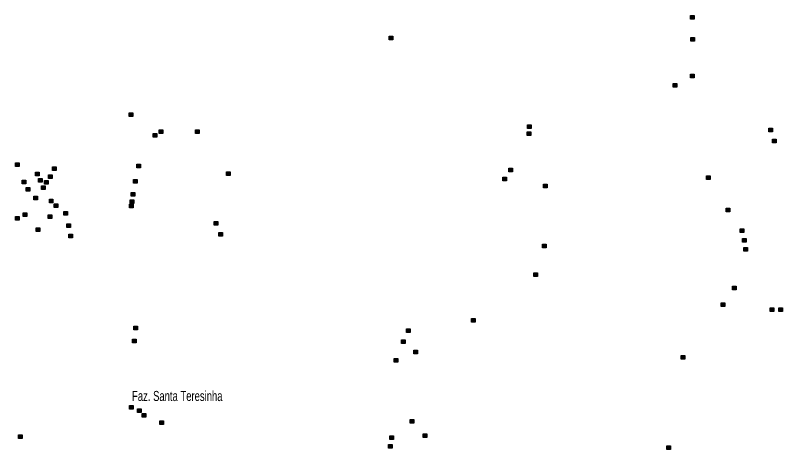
# Model space of a CAD drawing. Extents: x 265.7 to 292.1, y 7676.2 to 7704.2.
# Drawn here: x 272.33 to 278.4, y 7697.21 to 7700.64 of the extents above; entities that cross this region are included whole.
import ezdxf

# ---------------------------------------------------------------- set-up
doc = ezdxf.new("R2010")
doc.units = 0
doc.header["$LTSCALE"] = 0.032
doc.layers.add('2', color=7, linetype='Continuous', lineweight=25)
doc.layers.add('61', color=7, linetype='Continuous')

msp = doc.modelspace()

# ---------------------------------------------------------------- hatches: boundary and pattern name
at = {"layer": '2'}
for points in [[(277.6696, 7700.6412), (277.6986, 7700.6412), (277.6986, 7700.6122), (277.6696, 7700.6122)], [(275.2848, 7700.4775), (275.3138, 7700.4775), (275.3138, 7700.4485), (275.2848, 7700.4485)], [(277.6727, 7700.4669), (277.7017, 7700.4669), (277.7017, 7700.4379), (277.6727, 7700.4379)], [(277.6703, 7700.1772), (277.6993, 7700.1772), (277.6993, 7700.1482), (277.6703, 7700.1482)], [(277.5324, 7700.103), (277.5614, 7700.103), (277.5614, 7700.074), (277.5324, 7700.074)], [(273.2299, 7699.8705), (273.2589, 7699.8705), (273.2589, 7699.8415), (273.2299, 7699.8415)], [(276.3799, 7699.7753), (276.4089, 7699.7753), (276.4089, 7699.7463), (276.3799, 7699.7463)], [(273.4656, 7699.7349), (273.4946, 7699.7349), (273.4946, 7699.7059), (273.4656, 7699.7059)], [(273.7529, 7699.7366), (273.7819, 7699.7366), (273.7819, 7699.7076), (273.7529, 7699.7076)], [(276.3776, 7699.7213), (276.4066, 7699.7213), (276.4066, 7699.6923), (276.3776, 7699.6923)], [(278.291, 7699.7478), (278.32, 7699.7478), (278.32, 7699.7188), (278.291, 7699.7188)], [(273.4189, 7699.706), (273.4479, 7699.706), (273.4479, 7699.677), (273.4189, 7699.677)], [(278.3176, 7699.6623), (278.3466, 7699.6623), (278.3466, 7699.6333), (278.3176, 7699.6333)], [(272.3302, 7699.4743), (272.3592, 7699.4743), (272.3592, 7699.4453), (272.3302, 7699.4453)], [(273.2896, 7699.4653), (273.3186, 7699.4653), (273.3186, 7699.4363), (273.2896, 7699.4363)], [(272.6223, 7699.4428), (272.6513, 7699.4428), (272.6513, 7699.4138), (272.6223, 7699.4138)], [(273.9983, 7699.4041), (274.0273, 7699.4041), (274.0273, 7699.3751), (273.9983, 7699.3751)], [(276.2321, 7699.4315), (276.2611, 7699.4315), (276.2611, 7699.4025), (276.2321, 7699.4025)], [(272.4891, 7699.4008), (272.5181, 7699.4008), (272.5181, 7699.3718), (272.4891, 7699.3718)], [(272.5117, 7699.35), (272.5407, 7699.35), (272.5407, 7699.321), (272.5117, 7699.321)], [(272.5899, 7699.3788), (272.6189, 7699.3788), (272.6189, 7699.3498), (272.5899, 7699.3498)], [(273.2622, 7699.3436), (273.2912, 7699.3436), (273.2912, 7699.3146), (273.2622, 7699.3146)], [(276.1854, 7699.3613), (276.2144, 7699.3613), (276.2144, 7699.3323), (276.1854, 7699.3323)], [(277.7954, 7699.3719), (277.8244, 7699.3719), (277.8244, 7699.3429), (277.7954, 7699.3429)], [(272.3818, 7699.3379), (272.4108, 7699.3379), (272.4108, 7699.3089), (272.3818, 7699.3089)], [(272.5343, 7699.292), (272.5633, 7699.292), (272.5633, 7699.263), (272.5343, 7699.263)], [(272.5585, 7699.3355), (272.5875, 7699.3355), (272.5875, 7699.3065), (272.5585, 7699.3065)], [(276.5074, 7699.3048), (276.5364, 7699.3048), (276.5364, 7699.2758), (276.5074, 7699.2758)], [(272.4141, 7699.279), (272.4431, 7699.279), (272.4431, 7699.25), (272.4141, 7699.25)], [(273.2438, 7699.2394), (273.2728, 7699.2394), (273.2728, 7699.2104), (273.2438, 7699.2104)], [(272.4746, 7699.2113), (272.5036, 7699.2113), (272.5036, 7699.1823), (272.4746, 7699.1823)], [(272.5974, 7699.1871), (272.6264, 7699.1871), (272.6264, 7699.1581), (272.5974, 7699.1581)], [(273.2381, 7699.1829), (273.2671, 7699.1829), (273.2671, 7699.1539), (273.2381, 7699.1539)], [(272.6347, 7699.15), (272.6637, 7699.15), (272.6637, 7699.121), (272.6347, 7699.121)], [(273.2316, 7699.1467), (273.2606, 7699.1467), (273.2606, 7699.1177), (273.2316, 7699.1177)], [(277.952, 7699.1167), (277.981, 7699.1167), (277.981, 7699.0877), (277.952, 7699.0877)], [(272.3285, 7699.0507), (272.3575, 7699.0507), (272.3575, 7699.0217), (272.3285, 7699.0217)], [(272.3898, 7699.0796), (272.4188, 7699.0796), (272.4188, 7699.0506), (272.3898, 7699.0506)], [(272.5891, 7699.0635), (272.6181, 7699.0635), (272.6181, 7699.0345), (272.5891, 7699.0345)], [(272.7118, 7699.0893), (272.7408, 7699.0893), (272.7408, 7699.0603), (272.7118, 7699.0603)], [(272.7368, 7698.9925), (272.7658, 7698.9925), (272.7658, 7698.9635), (272.7368, 7698.9635)], [(273.9015, 7699.0102), (273.9305, 7699.0102), (273.9305, 7698.9812), (273.9015, 7698.9812)], [(272.4922, 7698.9602), (272.5212, 7698.9602), (272.5212, 7698.9312), (272.4922, 7698.9312)], [(273.9394, 7698.9248), (273.9684, 7698.9248), (273.9684, 7698.8958), (273.9394, 7698.8958)], [(278.0642, 7698.9538), (278.0932, 7698.9538), (278.0932, 7698.9248), (278.0642, 7698.9248)], [(272.7505, 7698.9102), (272.7795, 7698.9102), (272.7795, 7698.8812), (272.7505, 7698.8812)], [(278.0803, 7698.8763), (278.1093, 7698.8763), (278.1093, 7698.8473), (278.0803, 7698.8473)], [(276.4986, 7698.8311), (276.5276, 7698.8311), (276.5276, 7698.8021), (276.4986, 7698.8021)], [(278.0908, 7698.8053), (278.1198, 7698.8053), (278.1198, 7698.7763), (278.0908, 7698.7763)], [(276.43, 7698.6051), (276.459, 7698.6051), (276.459, 7698.5761), (276.43, 7698.5761)], [(278.0021, 7698.4986), (278.0311, 7698.4986), (278.0311, 7698.4696), (278.0021, 7698.4696)], [(277.9125, 7698.3669), (277.9415, 7698.3669), (277.9415, 7698.3379), (277.9125, 7698.3379)], [(278.2999, 7698.3275), (278.3289, 7698.3275), (278.3289, 7698.2985), (278.2999, 7698.2985)], [(278.3701, 7698.329), (278.3991, 7698.329), (278.3991, 7698.3), (278.3701, 7698.3)], [(275.9385, 7698.2428), (275.9675, 7698.2428), (275.9675, 7698.2138), (275.9385, 7698.2138)], [(273.2671, 7698.1823), (273.2961, 7698.1823), (273.2961, 7698.1533), (273.2671, 7698.1533)], [(275.4236, 7698.1628), (275.4526, 7698.1628), (275.4526, 7698.1338), (275.4236, 7698.1338)], [(273.2566, 7698.0805), (273.2856, 7698.0805), (273.2856, 7698.0515), (273.2566, 7698.0515)], [(275.3848, 7698.074), (275.4138, 7698.074), (275.4138, 7698.045), (275.3848, 7698.045)], [(275.4817, 7697.9925), (275.5107, 7697.9925), (275.5107, 7697.9635), (275.4817, 7697.9635)], [(277.5969, 7697.9514), (277.6259, 7697.9514), (277.6259, 7697.9224), (277.5969, 7697.9224)], [(275.3267, 7697.9281), (275.3557, 7697.9281), (275.3557, 7697.8991), (275.3267, 7697.8991)], [(273.2323, 7697.5559), (273.2613, 7697.5559), (273.2613, 7697.5269), (273.2323, 7697.5269)], [(273.2938, 7697.5286), (273.3228, 7697.5286), (273.3228, 7697.4996), (273.2938, 7697.4996)], [(273.3309, 7697.4921), (273.3599, 7697.4921), (273.3599, 7697.4631), (273.3309, 7697.4631)], [(273.4721, 7697.4332), (273.5011, 7697.4332), (273.5011, 7697.4042), (273.4721, 7697.4042)], [(275.4526, 7697.4462), (275.4816, 7697.4462), (275.4816, 7697.4172), (275.4526, 7697.4172)], [(272.3535, 7697.3227), (272.3825, 7697.3227), (272.3825, 7697.2937), (272.3535, 7697.2937)], [(275.292, 7697.3162), (275.321, 7697.3162), (275.321, 7697.2872), (275.292, 7697.2872)], [(275.5543, 7697.3324), (275.5833, 7697.3324), (275.5833, 7697.3034), (275.5543, 7697.3034)], [(275.2808, 7697.2485), (275.3098, 7697.2485), (275.3098, 7697.2195), (275.2808, 7697.2195)], [(277.4816, 7697.2355), (277.5106, 7697.2355), (277.5106, 7697.2065), (277.4816, 7697.2065)]]:
    msp.add_hatch(color=256, dxfattribs=at).paths.add_polyline_path(points)

# ---------------------------------------------------------------- linework, layer by layer
for points in [[(277.6696, 7700.6412), (277.6986, 7700.6412), (277.6986, 7700.6122), (277.6696, 7700.6122)], [(275.2848, 7700.4775), (275.3138, 7700.4775), (275.3138, 7700.4485), (275.2848, 7700.4485)], [(277.6727, 7700.4669), (277.7017, 7700.4669), (277.7017, 7700.4379), (277.6727, 7700.4379)], [(277.6703, 7700.1772), (277.6993, 7700.1772), (277.6993, 7700.1482), (277.6703, 7700.1482)], [(277.5324, 7700.103), (277.5614, 7700.103), (277.5614, 7700.074), (277.5324, 7700.074)], [(273.2299, 7699.8705), (273.2589, 7699.8705), (273.2589, 7699.8415), (273.2299, 7699.8415)], [(276.3799, 7699.7753), (276.4089, 7699.7753), (276.4089, 7699.7463), (276.3799, 7699.7463)], [(273.4656, 7699.7349), (273.4946, 7699.7349), (273.4946, 7699.7059), (273.4656, 7699.7059)], [(273.7529, 7699.7366), (273.7819, 7699.7366), (273.7819, 7699.7076), (273.7529, 7699.7076)], [(276.3776, 7699.7213), (276.4066, 7699.7213), (276.4066, 7699.6923), (276.3776, 7699.6923)], [(278.291, 7699.7478), (278.32, 7699.7478), (278.32, 7699.7188), (278.291, 7699.7188)], [(273.4189, 7699.706), (273.4479, 7699.706), (273.4479, 7699.677), (273.4189, 7699.677)], [(278.3176, 7699.6623), (278.3466, 7699.6623), (278.3466, 7699.6333), (278.3176, 7699.6333)], [(272.3302, 7699.4743), (272.3592, 7699.4743), (272.3592, 7699.4453), (272.3302, 7699.4453)], [(273.2896, 7699.4653), (273.3186, 7699.4653), (273.3186, 7699.4363), (273.2896, 7699.4363)], [(272.6223, 7699.4428), (272.6513, 7699.4428), (272.6513, 7699.4138), (272.6223, 7699.4138)], [(273.9983, 7699.4041), (274.0273, 7699.4041), (274.0273, 7699.3751), (273.9983, 7699.3751)], [(276.2321, 7699.4315), (276.2611, 7699.4315), (276.2611, 7699.4025), (276.2321, 7699.4025)], [(272.4891, 7699.4008), (272.5181, 7699.4008), (272.5181, 7699.3718), (272.4891, 7699.3718)], [(272.5117, 7699.35), (272.5407, 7699.35), (272.5407, 7699.321), (272.5117, 7699.321)], [(272.5899, 7699.3788), (272.6189, 7699.3788), (272.6189, 7699.3498), (272.5899, 7699.3498)], [(273.2622, 7699.3436), (273.2912, 7699.3436), (273.2912, 7699.3146), (273.2622, 7699.3146)], [(276.1854, 7699.3613), (276.2144, 7699.3613), (276.2144, 7699.3323), (276.1854, 7699.3323)], [(277.7954, 7699.3719), (277.8244, 7699.3719), (277.8244, 7699.3429), (277.7954, 7699.3429)], [(272.3818, 7699.3379), (272.4108, 7699.3379), (272.4108, 7699.3089), (272.3818, 7699.3089)], [(272.5343, 7699.292), (272.5633, 7699.292), (272.5633, 7699.263), (272.5343, 7699.263)], [(272.5585, 7699.3355), (272.5875, 7699.3355), (272.5875, 7699.3065), (272.5585, 7699.3065)], [(276.5074, 7699.3048), (276.5364, 7699.3048), (276.5364, 7699.2758), (276.5074, 7699.2758)], [(272.4141, 7699.279), (272.4431, 7699.279), (272.4431, 7699.25), (272.4141, 7699.25)], [(273.2438, 7699.2394), (273.2728, 7699.2394), (273.2728, 7699.2104), (273.2438, 7699.2104)], [(272.4746, 7699.2113), (272.5036, 7699.2113), (272.5036, 7699.1823), (272.4746, 7699.1823)], [(272.5974, 7699.1871), (272.6264, 7699.1871), (272.6264, 7699.1581), (272.5974, 7699.1581)], [(273.2381, 7699.1829), (273.2671, 7699.1829), (273.2671, 7699.1539), (273.2381, 7699.1539)], [(272.6347, 7699.15), (272.6637, 7699.15), (272.6637, 7699.121), (272.6347, 7699.121)], [(273.2316, 7699.1467), (273.2606, 7699.1467), (273.2606, 7699.1177), (273.2316, 7699.1177)], [(277.952, 7699.1167), (277.981, 7699.1167), (277.981, 7699.0877), (277.952, 7699.0877)], [(272.3285, 7699.0507), (272.3575, 7699.0507), (272.3575, 7699.0217), (272.3285, 7699.0217)], [(272.3898, 7699.0796), (272.4188, 7699.0796), (272.4188, 7699.0506), (272.3898, 7699.0506)], [(272.5891, 7699.0635), (272.6181, 7699.0635), (272.6181, 7699.0345), (272.5891, 7699.0345)], [(272.7118, 7699.0893), (272.7408, 7699.0893), (272.7408, 7699.0603), (272.7118, 7699.0603)], [(272.7368, 7698.9925), (272.7658, 7698.9925), (272.7658, 7698.9635), (272.7368, 7698.9635)], [(273.9015, 7699.0102), (273.9305, 7699.0102), (273.9305, 7698.9812), (273.9015, 7698.9812)], [(272.4922, 7698.9602), (272.5212, 7698.9602), (272.5212, 7698.9312), (272.4922, 7698.9312)], [(273.9394, 7698.9248), (273.9684, 7698.9248), (273.9684, 7698.8958), (273.9394, 7698.8958)], [(278.0642, 7698.9538), (278.0932, 7698.9538), (278.0932, 7698.9248), (278.0642, 7698.9248)], [(272.7505, 7698.9102), (272.7795, 7698.9102), (272.7795, 7698.8812), (272.7505, 7698.8812)], [(278.0803, 7698.8763), (278.1093, 7698.8763), (278.1093, 7698.8473), (278.0803, 7698.8473)], [(276.4986, 7698.8311), (276.5276, 7698.8311), (276.5276, 7698.8021), (276.4986, 7698.8021)], [(278.0908, 7698.8053), (278.1198, 7698.8053), (278.1198, 7698.7763), (278.0908, 7698.7763)], [(276.43, 7698.6051), (276.459, 7698.6051), (276.459, 7698.5761), (276.43, 7698.5761)], [(278.0021, 7698.4986), (278.0311, 7698.4986), (278.0311, 7698.4696), (278.0021, 7698.4696)], [(277.9125, 7698.3669), (277.9415, 7698.3669), (277.9415, 7698.3379), (277.9125, 7698.3379)], [(278.2999, 7698.3275), (278.3289, 7698.3275), (278.3289, 7698.2985), (278.2999, 7698.2985)], [(278.3701, 7698.329), (278.3991, 7698.329), (278.3991, 7698.3), (278.3701, 7698.3)], [(275.9385, 7698.2428), (275.9675, 7698.2428), (275.9675, 7698.2138), (275.9385, 7698.2138)], [(273.2671, 7698.1823), (273.2961, 7698.1823), (273.2961, 7698.1533), (273.2671, 7698.1533)], [(275.4236, 7698.1628), (275.4526, 7698.1628), (275.4526, 7698.1338), (275.4236, 7698.1338)], [(273.2566, 7698.0805), (273.2856, 7698.0805), (273.2856, 7698.0515), (273.2566, 7698.0515)], [(275.3848, 7698.074), (275.4138, 7698.074), (275.4138, 7698.045), (275.3848, 7698.045)], [(275.4817, 7697.9925), (275.5107, 7697.9925), (275.5107, 7697.9635), (275.4817, 7697.9635)], [(277.5969, 7697.9514), (277.6259, 7697.9514), (277.6259, 7697.9224), (277.5969, 7697.9224)], [(275.3267, 7697.9281), (275.3557, 7697.9281), (275.3557, 7697.8991), (275.3267, 7697.8991)], [(273.2323, 7697.5559), (273.2613, 7697.5559), (273.2613, 7697.5269), (273.2323, 7697.5269)], [(273.2938, 7697.5286), (273.3228, 7697.5286), (273.3228, 7697.4996), (273.2938, 7697.4996)], [(273.3309, 7697.4921), (273.3599, 7697.4921), (273.3599, 7697.4631), (273.3309, 7697.4631)], [(273.4721, 7697.4332), (273.5011, 7697.4332), (273.5011, 7697.4042), (273.4721, 7697.4042)], [(275.4526, 7697.4462), (275.4816, 7697.4462), (275.4816, 7697.4172), (275.4526, 7697.4172)], [(272.3535, 7697.3227), (272.3825, 7697.3227), (272.3825, 7697.2937), (272.3535, 7697.2937)], [(275.292, 7697.3162), (275.321, 7697.3162), (275.321, 7697.2872), (275.292, 7697.2872)], [(275.5543, 7697.3324), (275.5833, 7697.3324), (275.5833, 7697.3034), (275.5543, 7697.3034)], [(275.2808, 7697.2485), (275.3098, 7697.2485), (275.3098, 7697.2195), (275.2808, 7697.2195)], [(277.4816, 7697.2355), (277.5106, 7697.2355), (277.5106, 7697.2065), (277.4816, 7697.2065)]]:
    msp.add_lwpolyline(points, close=True, dxfattribs=at)

# ---------------------------------------------------------------- texts
at = {"layer": '61', "width": 0.7}
msp.add_text('Faz. Santa Teresinha', height=0.08, dxfattribs=at).set_placement((273.2517, 7697.591))

doc.saveas('drawing.dxf')
